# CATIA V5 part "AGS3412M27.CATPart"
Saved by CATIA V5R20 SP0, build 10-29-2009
Part number: AGS3412M27
Definition: NONE
Nomenclature: AGS3412M27
Source: Unknown
Description: AGS3412M27
Bounding box of the stored display mesh (mm): x -33 to 35, y -32.5 to 32.5, z -32.5 to 32.5
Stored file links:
  C:\Users\Utente\Desktop\IO LAVORO\3D X SITO CF\X SITO\PLASTICA\AGS\AGS3412M27.CATPart
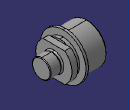
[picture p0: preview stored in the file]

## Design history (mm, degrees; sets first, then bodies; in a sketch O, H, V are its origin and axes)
Body1 "AGS3412M27" (main body)
  Solid1: solid without history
